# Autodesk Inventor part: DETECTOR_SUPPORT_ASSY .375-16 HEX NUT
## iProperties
Shininess: 64.0
Length Units: 11272
Angle Units: 11279
Time Units: 11290
Mass Units: 11286
Length Display Precision: 3
Angle Display Precision: 2
Compacted: True
Part Number: DETECTOR_SUPPORT_ASSY .375-16 HEX NUT
Document SubType Name: Modeling
Created: 2004-08
Designer: John Blackburn
Material: STAINLESS_STEEL, AUSTENITIC
Manufacturer: Standard
Standards Organization: Custom
Density: 0.0
Volumn: 0.0
Area: 0.0
PropertySet Name: Model Information
Control State: 0
Master: False
Checked Out: False
Author: John Blackburn
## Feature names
1. Base1
